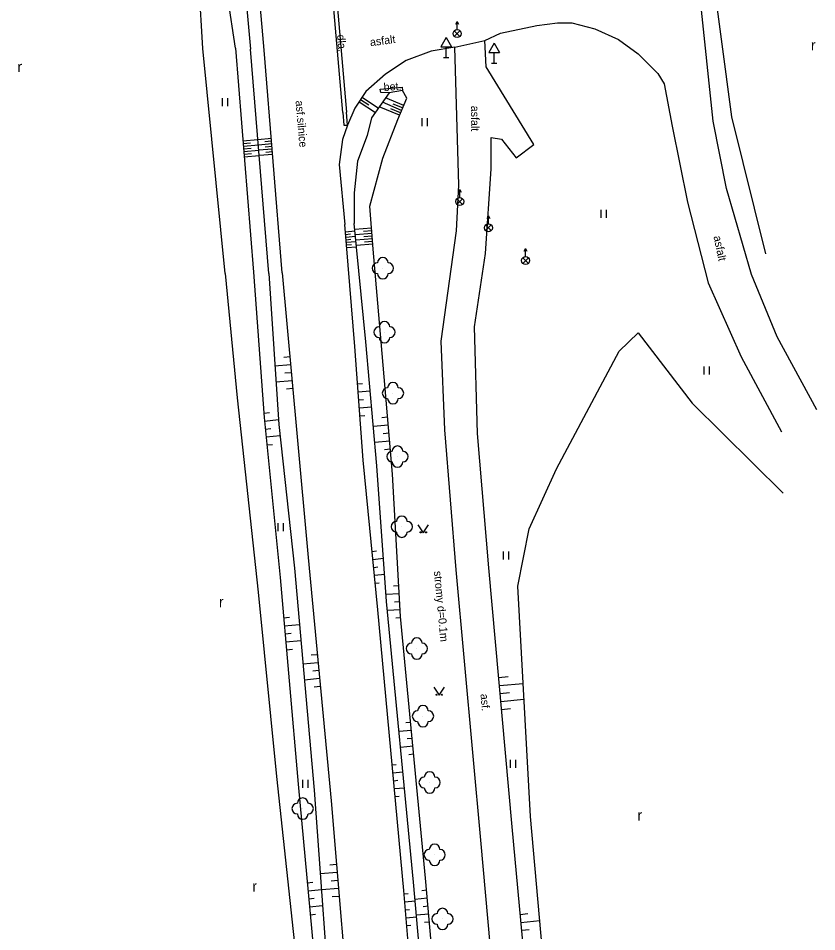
# Model space of a CAD drawing. Extents: x -545714 to -535419, y -1201788 to -1194297.
# Drawn here: x -543656.7 to -543581.9, y -1195950.8 to -1195865.2 of the extents above; entities that cross this region are included whole.
import ezdxf

# ---------------------------------------------------------------- set-up
doc = ezdxf.new("R2010")
doc.units = 0
for name, color, linetype in [('Vrstva 10', 7, 'Continuous'), ('Vrstva 11', 7, 'Continuous'), ('Vrstva 12', 7, 'Continuous'), ('Vrstva 13', 7, 'Continuous'), ('Vrstva 15', 7, 'Continuous'), ('Vrstva 2', 7, 'Continuous'), ('Vrstva 3', 7, 'Continuous')]:
    doc.layers.add(name, color=color, linetype=linetype)

msp = doc.modelspace()

# ---------------------------------------------------------------- linework, layer by layer
at = {"layer": 'Vrstva 10'}
for p, q in [((-543616.66, -1195866.984), (-543617.16, -1195867.85)), ((-543616.66, -1195866.984), (-543616.16, -1195867.85)), ((-543612.16, -1195867.504), (-543612.66, -1195868.37)), ((-543612.16, -1195867.504), (-543611.66, -1195868.37)), ((-543617.16, -1195867.85), (-543616.16, -1195867.85)), ((-543616.66, -1195868.85), (-543616.66, -1195867.85)), ((-543612.66, -1195868.37), (-543611.66, -1195868.37)), ((-543612.16, -1195869.37), (-543612.16, -1195868.37)), ((-543616.91, -1195868.85), (-543616.41, -1195868.85)), ((-543612.41, -1195869.37), (-543611.91, -1195869.37))]:
    msp.add_line(p, q, dxfattribs=at)
msp.add_lwpolyline([(-543620.74, -1195871.96), (-543622, -1195872.15), (-543622.77, -1195872.14), (-543622.84, -1195871.81), (-543620.77, -1195871.62), (-543620.74, -1195871.96)], dxfattribs=at)
at = {"layer": 'Vrstva 11'}
for p, q in [((-543591.66, -1195874.83), (-543593.88, -1195853.34)), ((-543626.35, -1195874.01), (-543627.36, -1195862.11)), ((-543615.86, -1195867.87), (-543613.03, -1195867.25)), ((-543595.48, -1195875.3), (-543594.04, -1195882.42))]:
    msp.add_line(p, q, dxfattribs=at)
for points in [[(-543632.01, -1195889.02), (-543633.7, -1195868.17), (-543634.58, -1195858.11), (-543635.22, -1195849.91), (-543636.8, -1195836.16)], [(-543627.7, -1195858.55), (-543627.4, -1195858.54), (-543627.01, -1195862.06), (-543626.01, -1195873.96)], [(-543613.03, -1195867.25), (-543611.57, -1195866.57), (-543608.17, -1195865.84), (-543606.23, -1195865.59), (-543604.9, -1195865.6), (-543602.73, -1195866.18), (-543600.52, -1195867.18), (-543598.67, -1195868.5), (-543596.82, -1195870.36), (-543596.24, -1195871.31), (-543595.48, -1195875.3)], [(-543607.43, -1196037.02), (-543606.28, -1196019.77), (-543606.3, -1196009), (-543606.5, -1195995.43), (-543607.06, -1195984.44), (-543608.01, -1195967.52), (-543610.49, -1195940.94), (-543612.66, -1195916.66), (-543613.72, -1195904.08), (-543614, -1195894.09), (-543612.96, -1195887.23), (-543612.45, -1195879.29), (-543612.44, -1195876.36), (-543611.47, -1195876.49), (-543610.1, -1195878.26), (-543608.46, -1195876.99), (-543612.9, -1195869.72), (-543613.03, -1195867.25)], [(-543632.41, -1196211.07), (-543630.37, -1196193.32), (-543624.96, -1196151.17), (-543622.81, -1196132.43), (-543618.85, -1196100.43), (-543615.34, -1196072.49), (-543612.05, -1196046.99), (-543610.57, -1196036.97), (-543609.35, -1196020.42), (-543609.38, -1196008.52), (-543609.53, -1195995.3), (-543610, -1195984.65), (-543611.08, -1195968.31), (-543613.38, -1195942.54), (-543615.71, -1195916.87), (-543616.79, -1195903.73), (-543617.14, -1195895.44), (-543615.68, -1195885.08), (-543615.46, -1195880.81), (-543615.86, -1195867.87)], [(-543615.86, -1195867.87), (-543618.05, -1195868.25), (-543620.42, -1195869.12), (-543622.35, -1195870.41), (-543624.18, -1195872.04), (-543625.2, -1195873.6), (-543625.89, -1195875.18), (-543626.36, -1195876.55), (-543626.68, -1195878.88), (-543626.15, -1195884.51)], [(-543626.35, -1195874.01), (-543626.25, -1195875.18), (-543625.89, -1195875.18), (-543626.01, -1195873.96)], [(-543581.95, -1195901.87), (-543585.67, -1195895.04), (-543588.06, -1195889.18), (-543590.41, -1195881.14), (-543591.66, -1195874.83)], [(-543594.04, -1195882.42), (-543592.12, -1195889.97), (-543589.04, -1195896.91), (-543585.26, -1195903.93)], [(-543639.09, -1196203.64), (-543635.02, -1196171.2), (-543630.55, -1196134.22), (-543626.42, -1196101.45), (-543622.95, -1196075.4), (-543619.74, -1196048.22), (-543618.21, -1196036.42), (-543616.96, -1196023.24), (-543616.56, -1196007.59), (-543616.68, -1195997.82), (-543617.53, -1195985.22), (-543618.61, -1195971.27), (-543620.62, -1195946.9), (-543623.05, -1195920.62), (-543624.43, -1195906.58), (-543625.23, -1195895.93), (-543626.15, -1195884.51)], [(-543632.01, -1195889.02), (-543630.66, -1195904.04), (-543629.59, -1195915.71), (-543627.44, -1195938.51), (-543625.46, -1195962.01), (-543624.21, -1195975.84), (-543623.14, -1195988.77), (-543622.74, -1195996.52), (-543622.61, -1196011.77), (-543622.88, -1196018.77), (-543623.58, -1196028.52), (-543624.79, -1196039.27), (-543627.41, -1196061.04), (-543629.27, -1196076.23), (-543632.15, -1196098.41), (-543634.76, -1196118.38), (-543637.1, -1196136.86), (-543638.96, -1196152.81), (-543641.47, -1196173.25), (-543643.67, -1196191.48), (-543644.99, -1196202.76)]]:
    msp.add_lwpolyline(points, dxfattribs=at)
at = {"layer": 'Vrstva 12'}
for points in [[(-543637.35, -1195889.08), (-543639.44, -1195868.02), (-543640.15, -1195856.37), (-543640.47, -1195849.63), (-543641.68, -1195837.02)], [(-543596.85, -1195847.26), (-543593.73, -1195848.08), (-543592.78, -1195853.03), (-543589.93, -1195874.41), (-543586.75, -1195887.25)], [(-543637.35, -1195889.08), (-543636.25, -1195900.75), (-543634.27, -1195918.95), (-543632.55, -1195936.22), (-543630.06, -1195959.48), (-543628.32, -1195978.08), (-543627.64, -1195989.06), (-543627.13, -1195998.35), (-543627.3, -1196008.65), (-543627.81, -1196019.91), (-543628.52, -1196027.23), (-543629.59, -1196040.43), (-543631.56, -1196057.77), (-543633.61, -1196077.67), (-543635.95, -1196095.36), (-543638.88, -1196118.45), (-543640.59, -1196133.76), (-543643.14, -1196154.34), (-543645.07, -1196170.53), (-543648, -1196190.91), (-543649.65, -1196200.28)], [(-543620.94, -1196214.98), (-543624.31, -1196211.9), (-543626.03, -1196206.25), (-543625.47, -1196195.96), (-543620.17, -1196152.27), (-543617.52, -1196130.8), (-543613.54, -1196101.25), (-543610.23, -1196073.03), (-543606.7, -1196046.58), (-543605.55, -1196038.14), (-543604.25, -1196019.22), (-543604.31, -1196010.39), (-543604.8, -1195995.59), (-543605.27, -1195985.05), (-543606.35, -1195966.98), (-543608.76, -1195939.98), (-543609.96, -1195918.4), (-543608.87, -1195913.01), (-543606.32, -1195907.39), (-543600.46, -1195896.38), (-543598.68, -1195894.64), (-543593.62, -1195901.24), (-543585.09, -1195909.68)]]:
    msp.add_lwpolyline(points, dxfattribs=at)
for centre in [(-543622.59, -1195888.6), (-543622.44, -1195894.59), (-543621.64, -1195900.31), (-543621.22, -1195906.25), (-543620.81, -1195912.82), (-543619.41, -1195924.24), (-543618.83, -1195930.58), (-543618.21, -1195936.79), (-543630.1, -1195939.24), (-543617.74, -1195943.57), (-543617, -1195949.58)]:
    msp.add_circle(centre, 0.0005, dxfattribs=at)
for centre, start, end in [((-543622.59, -1195888.1), 0, 179.99999), ((-543623.09, -1195888.6), 89.99999, 269.99999), ((-543622.09, -1195888.6), 270, 89.99999), ((-543622.59, -1195889.1), 179.99999, 359.99999), ((-543622.44, -1195894.09), 0, 179.99999), ((-543622.94, -1195894.59), 89.99999, 269.99999), ((-543621.94, -1195894.59), 270, 89.99999), ((-543622.44, -1195895.09), 179.99999, 359.99999), ((-543622.14, -1195900.31), 89.99999, 269.99999), ((-543621.64, -1195899.81), 0, 179.99999), ((-543621.14, -1195900.31), 270, 89.99999), ((-543621.64, -1195900.81), 179.99999, 359.99999), ((-543621.72, -1195906.25), 89.99999, 269.99999), ((-543621.22, -1195905.75), 0, 179.99999), ((-543620.72, -1195906.25), 270, 89.99999), ((-543621.22, -1195906.75), 179.99999, 359.99999), ((-543620.81, -1195912.32), 0, 179.99999), ((-543621.31, -1195912.82), 89.99999, 269.99999), ((-543620.31, -1195912.82), 270, 89.99999), ((-543620.81, -1195913.32), 179.99999, 359.99999), ((-543619.91, -1195924.24), 89.99999, 269.99999), ((-543619.41, -1195923.74), 0, 179.99999), ((-543618.91, -1195924.24), 270, 89.99999), ((-543619.41, -1195924.74), 179.99999, 359.99999), ((-543618.83, -1195930.08), 0, 179.99999), ((-543619.33, -1195930.58), 89.99999, 269.99999), ((-543618.33, -1195930.58), 270, 89.99999), ((-543618.83, -1195931.08), 179.99999, 359.99999), ((-543618.21, -1195936.29), 0, 179.99999), ((-543618.71, -1195936.79), 89.99999, 269.99999), ((-543617.71, -1195936.79), 270, 89.99999), ((-543618.21, -1195937.29), 179.99999, 359.99999), ((-543630.1, -1195938.74), 0, 179.99999), ((-543630.6, -1195939.24), 89.99999, 269.99999), ((-543629.6, -1195939.24), 270, 89.99999), ((-543630.1, -1195939.74), 179.99999, 359.99999), ((-543617.74, -1195943.07), 0, 179.99999), ((-543618.24, -1195943.57), 89.99999, 269.99999), ((-543617.24, -1195943.57), 270, 89.99999), ((-543617.74, -1195944.07), 179.99999, 359.99999), ((-543617, -1195949.08), 0, 179.99999), ((-543617.5, -1195949.58), 89.99999, 269.99999), ((-543616.5, -1195949.58), 270, 89.99999), ((-543617, -1195950.08), 179.99999, 359.99999)]:
    msp.add_arc(centre, 0.5, start, end, dxfattribs=at)
at = {"layer": 'Vrstva 13'}
for p, q in [((-543636.38, -1195867.99), (-543638.06, -1195856.87)), ((-543636.38, -1195867.99), (-543634.72, -1195888.98)), ((-543633.26, -1195889.08), (-543634.99, -1195868.06)), ((-543624.535, -1195872.583), (-543623, -1195873.587)), ((-543620.638, -1195873.347), (-543622.336, -1195872.633)), ((-543624.809, -1195873.002), (-543623.286, -1195873.997)), ((-543624.672, -1195872.793), (-543623.908, -1195873.292)), ((-543621.026, -1195874.269), (-543622.921, -1195873.473)), ((-543620.832, -1195873.808), (-543622.629, -1195873.053)), ((-543620.735, -1195873.577), (-543621.609, -1195873.21)), ((-543620.929, -1195874.038), (-543621.852, -1195873.65)), ((-543635.695, -1195876.65), (-543634.292, -1195876.539)), ((-543635.675, -1195876.899), (-543634.974, -1195876.843)), ((-543633.029, -1195876.451), (-543634.291, -1195876.553)), ((-543633.009, -1195876.7), (-543633.64, -1195876.751)), ((-543635.656, -1195877.148), (-543634.251, -1195877.037)), ((-543635.636, -1195877.397), (-543634.933, -1195877.342)), ((-543635.616, -1195877.646), (-543634.21, -1195877.535)), ((-543632.988, -1195876.95), (-543634.25, -1195877.052)), ((-543632.948, -1195877.448), (-543634.209, -1195877.55)), ((-543632.968, -1195877.199), (-543633.599, -1195877.25)), ((-543632.928, -1195877.697), (-543633.558, -1195877.748)), ((-543635.597, -1195877.896), (-543634.893, -1195877.84)), ((-543635.577, -1195878.145), (-543634.169, -1195878.034)), ((-543632.908, -1195877.946), (-543634.168, -1195878.048)), ((-543626.096, -1195885.175), (-543625.202, -1195885.103)), ((-543626.076, -1195885.425), (-543625.627, -1195885.388)), ((-543623.651, -1195884.847), (-543625.215, -1195884.974)), ((-543623.61, -1195885.345), (-543625.166, -1195885.472)), ((-543623.631, -1195885.096), (-543624.41, -1195885.159)), ((-543626.056, -1195885.674), (-543625.153, -1195885.601)), ((-543626.036, -1195885.923), (-543625.582, -1195885.886)), ((-543626.016, -1195886.172), (-543625.104, -1195886.099)), ((-543623.57, -1195885.843), (-543625.117, -1195885.97)), ((-543623.529, -1195886.342), (-543625.068, -1195886.467)), ((-543623.59, -1195885.594), (-543624.366, -1195885.657)), ((-543623.549, -1195886.092), (-543624.321, -1195886.155)), ((-543625.996, -1195886.421), (-543625.538, -1195886.384)), ((-543625.976, -1195886.67), (-543625.055, -1195886.596))]:
    msp.add_line(p, q, dxfattribs=at)
for points in [[(-543636.73, -1195850.3), (-543635.93, -1195857.75), (-543634.99, -1195868.06)], [(-543622, -1195872.15), (-543623.65, -1195874.52), (-543624.05, -1195876.15), (-543624.97, -1195878.56), (-543625.27, -1195881.52), (-543625.27, -1195884.41)], [(-543623.49, -1195886.82), (-543623.82, -1195882.78), (-543622.6, -1195878.28), (-543621.19, -1195874.66), (-543620.35, -1195872.66), (-543620.74, -1195871.96)], [(-543637.68, -1196204.91), (-543633.55, -1196170.77), (-543629.08, -1196133.41), (-543625.09, -1196102.26), (-543621.67, -1196075.01), (-543618.41, -1196048.88), (-543616.7, -1196036.73), (-543614.81, -1196022.52), (-543614.82, -1196007.8), (-543615.15, -1195997.35), (-543616.06, -1195985.01), (-543617.47, -1195971.56), (-543619.73, -1195946.13), (-543622.24, -1195919.83), (-543623.14, -1195907.11), (-543624.18, -1195895.5), (-543625.27, -1195884.41)], [(-543637.05, -1196204.96), (-543632.44, -1196170.19), (-543627.94, -1196133.03), (-543624.22, -1196102.84), (-543620.55, -1196074.64), (-543617.37, -1196049.43), (-543615.66, -1196036.82), (-543613.64, -1196022.43), (-543613.38, -1196008.04), (-543613.8, -1195996.84), (-543614.79, -1195985), (-543616.24, -1195972.22), (-543618.58, -1195945.75), (-543620.93, -1195921.24), (-543621.68, -1195907.9), (-543622.76, -1195895.51), (-543623.49, -1195886.82)], [(-543634.72, -1195888.98), (-543633.71, -1195902.59), (-543632.22, -1195917.58), (-543630.51, -1195936.95), (-543628.32, -1195960.9), (-543627.16, -1195976.56), (-543626.29, -1195988.96), (-543625.18, -1195997.54), (-543625.08, -1196010.41), (-543625.45, -1196019.37), (-543626.81, -1196027.23), (-543628.09, -1196039), (-543629.96, -1196058.78), (-543632.18, -1196076.05), (-543634.6, -1196096.72), (-543637.55, -1196118.36), (-543639.29, -1196135.15), (-543642.06, -1196154.03), (-543643.93, -1196171.42), (-543646.59, -1196191.4), (-543647.93, -1196200.94)], [(-543633.26, -1195889.08), (-543632.32, -1195903.25), (-543630.88, -1195916.7), (-543629.01, -1195937.51), (-543627.31, -1195961.18), (-543625.83, -1195976.22), (-543624.72, -1195988.72), (-543624.05, -1195997.08), (-543623.61, -1196011.03), (-543624.09, -1196019.16), (-543625.02, -1196027.87), (-543626.53, -1196039.42), (-543628.92, -1196059.75), (-543630.9, -1196076.27), (-543633.64, -1196097.53), (-543636.3, -1196118.46), (-543638.55, -1196135.87), (-543640.73, -1196153.47), (-543642.99, -1196172.25), (-543645.26, -1196191.46), (-543646.43, -1196201.58)], [(-543631.27, -1195896.89), (-543631.88, -1195896.95)], [(-543631.21, -1195897.64), (-543632.73, -1195897.77)], [(-543631.08, -1195899.14), (-543632.62, -1195899.27)], [(-543631.14, -1195898.39), (-543631.76, -1195898.44)], [(-543631.01, -1195899.88), (-543631.63, -1195899.94)], [(-543624.97, -1195899.43), (-543624.51, -1195899.4)], [(-543624.91, -1195900.18), (-543623.77, -1195900.09)], [(-543624.85, -1195900.93), (-543624.39, -1195900.89)], [(-543624.8, -1195901.67), (-543623.63, -1195901.59)], [(-543633.74, -1195902.17), (-543633.21, -1195902.13)], [(-543624.74, -1195902.42), (-543624.27, -1195902.39)], [(-543622.14, -1195902.57), (-543622.7, -1195902.62)], [(-543633.68, -1195902.92), (-543632.35, -1195902.79)], [(-543622.08, -1195903.32), (-543623.47, -1195903.44)], [(-543633.6, -1195903.67), (-543633.08, -1195903.61)], [(-543633.53, -1195904.41), (-543632.21, -1195904.28)], [(-543622.01, -1195904.07), (-543622.57, -1195904.11)], [(-543633.45, -1195905.16), (-543632.92, -1195905.11)], [(-543621.95, -1195904.81), (-543623.33, -1195904.93)], [(-543621.88, -1195905.56), (-543622.44, -1195905.61)], [(-543623.59, -1195915.13), (-543623.19, -1195915.09)], [(-543623.52, -1195915.88), (-543622.53, -1195915.78)], [(-543623.44, -1195916.63), (-543623.05, -1195916.59)], [(-543623.37, -1195917.37), (-543622.42, -1195917.28)], [(-543623.3, -1195918.12), (-543622.92, -1195918.08)], [(-543621.09, -1195918.36), (-543621.59, -1195918.39)], [(-543621.05, -1195919.11), (-543622.29, -1195919.18)], [(-543621.01, -1195919.86), (-543621.5, -1195919.89)], [(-543631.89, -1195921.36), (-543631.32, -1195921.31)], [(-543620.97, -1195920.61), (-543622.16, -1195920.68)], [(-543620.92, -1195921.36), (-543621.38, -1195921.4)], [(-543631.82, -1195922.11), (-543630.41, -1195921.99)], [(-543631.75, -1195922.86), (-543631.19, -1195922.81)], [(-543631.69, -1195923.6), (-543630.27, -1195923.48)], [(-543631.62, -1195924.35), (-543631.05, -1195924.3)], [(-543628.73, -1195924.82), (-543629.29, -1195924.87)], [(-543628.66, -1195925.57), (-543630.07, -1195925.7)], [(-543628.59, -1195926.31), (-543629.16, -1195926.37)], [(-543628.52, -1195927.06), (-543629.94, -1195927.19)], [(-543611.74, -1195926.95), (-543610.84, -1195926.87)], [(-543628.45, -1195927.81), (-543629.02, -1195927.86)], [(-543611.67, -1195927.69), (-543609.45, -1195927.5)], [(-543611.61, -1195928.44), (-543610.73, -1195928.36)], [(-543611.54, -1195929.19), (-543609.37, -1195928.99)], [(-543611.47, -1195929.94), (-543610.62, -1195929.86)], [(-543619.98, -1195931.16), (-543620.45, -1195931.21)], [(-543619.91, -1195931.91), (-543621.08, -1195932.02)], [(-543619.76, -1195933.4), (-543620.93, -1195933.52)], [(-543619.84, -1195932.66), (-543620.3, -1195932.7)], [(-543619.69, -1195934.15), (-543620.16, -1195934.2)], [(-543621.71, -1195935.12), (-543621.34, -1195935.09)], [(-543621.64, -1195935.87), (-543620.72, -1195935.78)], [(-543621.57, -1195936.62), (-543621.2, -1195936.58)], [(-543621.5, -1195937.36), (-543620.57, -1195937.28)], [(-543621.43, -1195938.11), (-543621.06, -1195938.08)], [(-543626.94, -1195944.48), (-543627.56, -1195944.53)], [(-543626.87, -1195945.22), (-543628.45, -1195945.36)], [(-543629.67, -1195946.19), (-543629.16, -1195946.14)], [(-543626.81, -1195945.97), (-543627.44, -1195946.03)], [(-543629.6, -1195946.94), (-543628.34, -1195946.82)], [(-543626.75, -1195946.72), (-543628.34, -1195946.85)], [(-543618.48, -1195946.89), (-543618.95, -1195946.93)], [(-543629.53, -1195947.68), (-543629.03, -1195947.64)], [(-543626.69, -1195947.47), (-543627.33, -1195947.52)], [(-543620.59, -1195947.21), (-543620.21, -1195947.18)], [(-543620.53, -1195947.96), (-543619.57, -1195947.88)], [(-543618.41, -1195947.64), (-543619.59, -1195947.74)], [(-543629.46, -1195948.43), (-543628.23, -1195948.32)], [(-543620.47, -1195948.71), (-543620.09, -1195948.68)], [(-543618.35, -1195948.38), (-543618.82, -1195948.43)], [(-543629.39, -1195949.18), (-543628.91, -1195949.13)], [(-543620.41, -1195949.46), (-543619.44, -1195949.38)], [(-543618.28, -1195949.13), (-543619.45, -1195949.23)], [(-543609.72, -1195949.15), (-543609.02, -1195949.08)], [(-543620.35, -1195950.2), (-543619.96, -1195950.17)], [(-543618.22, -1195949.88), (-543618.68, -1195949.92)], [(-543609.65, -1195949.9), (-543607.89, -1195949.73)], [(-543609.58, -1195950.64), (-543608.88, -1195950.58)]]:
    msp.add_lwpolyline(points, dxfattribs=at)
at = {"layer": 'Vrstva 2'}
for p, q in [((-543615.63, -1195866.235), (-543615.63, -1195865.485)), ((-543615.895, -1195866.874), (-543615.366, -1195866.346)), ((-543615.366, -1195866.878), (-543615.895, -1195866.346)), ((-543615.39, -1195881.975), (-543615.39, -1195881.225)), ((-543615.655, -1195882.614), (-543615.126, -1195882.086)), ((-543615.126, -1195882.618), (-543615.655, -1195882.086)), ((-543612.7, -1195884.435), (-543612.7, -1195883.685)), ((-543612.965, -1195885.074), (-543612.436, -1195884.546)), ((-543612.436, -1195885.078), (-543612.965, -1195884.546)), ((-543609.22, -1195887.505), (-543609.22, -1195886.755)), ((-543609.485, -1195888.144), (-543608.956, -1195887.616)), ((-543608.956, -1195888.148), (-543609.485, -1195887.616))]:
    msp.add_line(p, q, dxfattribs=at)
for points in [[(-543615.755, -1195865.735), (-543615.63, -1195865.485), (-543615.505, -1195865.735)], [(-543615.515, -1195881.475), (-543615.39, -1195881.225), (-543615.265, -1195881.475)], [(-543612.825, -1195883.935), (-543612.7, -1195883.685), (-543612.575, -1195883.935)], [(-543609.345, -1195887.005), (-543609.22, -1195886.755), (-543609.095, -1195887.005)]]:
    msp.add_lwpolyline(points, dxfattribs=at)
for centre in [(-543615.63, -1195866.61), (-543615.39, -1195882.35), (-543612.7, -1195884.81), (-543609.22, -1195887.88)]:
    msp.add_circle(centre, 0.375, dxfattribs=at)
at = {"layer": 'Vrstva 3'}
for p, q in [((-543637.61, -1195873.425), (-543637.61, -1195872.675)), ((-543637.11, -1195873.425), (-543637.11, -1195872.675)), ((-543618.9, -1195875.295), (-543618.9, -1195874.545)), ((-543618.4, -1195875.295), (-543618.4, -1195874.545)), ((-543602.13, -1195883.865), (-543602.13, -1195883.115)), ((-543601.63, -1195883.865), (-543601.63, -1195883.115)), ((-543592.49, -1195898.565), (-543592.49, -1195897.815)), ((-543591.99, -1195898.565), (-543591.99, -1195897.815)), ((-543632.39, -1195913.235), (-543632.39, -1195912.485)), ((-543631.89, -1195913.235), (-543631.89, -1195912.485)), ((-543611.28, -1195915.895), (-543611.28, -1195915.145)), ((-543610.78, -1195915.895), (-543610.78, -1195915.145)), ((-543610.63, -1195935.415), (-543610.63, -1195934.665)), ((-543610.13, -1195935.415), (-543610.13, -1195934.665)), ((-543630.09, -1195937.285), (-543630.09, -1195936.535)), ((-543629.59, -1195937.285), (-543629.59, -1195936.535))]:
    msp.add_line(p, q, dxfattribs=at)
for points in [[(-543619.3, -1195912.65), (-543618.8, -1195913.4), (-543618.3, -1195912.65)], [(-543617.81, -1195927.87), (-543617.31, -1195928.62), (-543616.81, -1195927.87)]]:
    msp.add_lwpolyline(points, dxfattribs=at)
for centre in [(-543619.05, -1195913.35), (-543618.55, -1195913.35), (-543617.56, -1195928.57), (-543617.06, -1195928.57)]:
    msp.add_circle(centre, 0.05, dxfattribs=at)

# ---------------------------------------------------------------- texts
at = {"layer": 'Vrstva 12'}
msp.add_text('stromy d=0.1m', height=0.75, rotation=275.33848, dxfattribs=at).set_placement((-543617.81, -1195917))
at = {"layer": 'Vrstva 15'}
for s, rotation, p in [('dla.', 274.69286, (-543626.88, -1195866.74)), ('asfalt', 7.50309, (-543623.75, -1195867.8)), ('bet.', 4.43267, (-543622.49, -1195872)), ('asf.silnice', 274.87828, (-543630.771, -1195872.912)), ('asfalt', 270, (-543614.32, -1195873.37)), ('asfalt', 281.7952, (-543591.62, -1195885.63)), ('asf.', 275.08048, (-543613.45, -1195928.51))]:
    msp.add_text(s, height=0.75, rotation=rotation, dxfattribs=at).set_placement(p)
at = {"layer": 'Vrstva 3'}
for p in [(-543582.498, -1195868.192), (-543656.828, -1195870.222), (-543637.948, -1195920.362), (-543598.738, -1195940.352), (-543634.818, -1195947.012)]:
    msp.add_text('r', height=1, dxfattribs=at).set_placement(p)

doc.saveas('drawing.dxf')
